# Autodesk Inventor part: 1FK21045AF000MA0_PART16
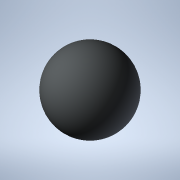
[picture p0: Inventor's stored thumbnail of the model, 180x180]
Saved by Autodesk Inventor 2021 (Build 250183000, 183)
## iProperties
Created: 2025-04
Part Number: 1FK21045AF000MA0_PART16
Material: Generic
Catalog Web Link: www.3dfindit.com
Description: -Servo synchronous motor
Document SubType Name: Modeling
Designer: psAdmin
Mass: 0.137258 g
Surface Area: 1.2868 cm^2
Volume: 0.137258 cm^3
Density: 1 g/cm^3
Appearance: PSOLRGB-212-217-219
Category: PARTsolutions
Title: 1FK21045AF000MA0_PART16
Author: Cadenas PARTsolutions
Comments: Servo synchronous motor
Sending System: PARTsolutions
Preprocessor: ST-DEVELOPER v19.3
PSOL_IDENT_0: {$CADENAS_DATA/23d-libs/siemens_ag/_cat_/8b/0a/1fk21045af000ma0.prj},216 {VTYP=3D},{NB=1FK21045AF000
PSOL_IDENT_1: MA0_PART16},{LINA=1FK21045AF000MA0_PART16},{NN=1FK21045AF000MA0_PART16},{NOPRJ=TRUE},{DATE=19.08.202
PSOL_IDENT_2: 5 14:00:48},{GEOMDATE=30.07.2025 02:00:28},{VERSION=},{LINEID=10},{WBVAR=},{WBNUMERIC=}  {NB=1FK2104
PSOL_IDENT_3: 5AF000MA0_PART16},{LINA=1FK21045AF000MA0_PART16},{KT=DUMMY},{PREVIEW=../../../_pool_/a9/69/p_d211_xx
PSOL_IDENT_4: _00818j.png},{DESCSHORT=SIMOTICS S-1FK2 HD, SINAMICS S210 3AC 400V-480V, 2.4 Nm, 3000 rpm},{DESCLONG=
PSOL_IDENT_5: SIMOTICS S-1FK2 HD servo motor M0=2.4 Nm; PN = 0.75 kW at nN=3000 rpm (380-480 V); PN = 0.375 kW at
PSOL_IDENT_6: nN=1500 rpm (200-240 V); degree of protection IP64; cylindrical shaft D19x40mm; absolute encoder 22-
PSOL_IDENT_7: bit + 12-bit multiturn (encoder AM22DQC); with OCC interface; plug size M17, rotatable; SIMOTICS S-1
PSOL_IDENT_8: FK2 servomotorfor a wide range of uses in industrial environments. SIMOTICS S‑1FK2 servomotors are c
PSOL_IDENT_9: ompact synchronous motors with a high dynamic performance that set themselves apart as a result of t
PSOL_IDENT_10: heir high power density, degree of protection and overload capability. The motors are available in t
PSOL_IDENT_11: wo variants: as High Dynamic variant (highest dynamic performance as a result of the low intrinsic m
PSOL_IDENT_12: oment of inertia for applications demanding a high dynamic performance with low moved masses) - and
PSOL_IDENT_13: as Compact variant (precise and stable closed-loop control for medium up to large moved masses as a
PSOL_IDENT_14: result of a medium intrinsic moment of inertia). SIMOTICSS‑1FK2 servomotors fully exploit their stre
PSOL_IDENT_15: ngths in a system with the SINAMICSS210 frequency converter and simple connection using the one cabl
PSOL_IDENT_16: e connection (OCC). Advantages include the short control and positioning times, fast and precise cor
PSOL_IDENT_17: rection of disturbing quantities as well as stable control with a high dynamic performance. The serv
PSOL_IDENT_18: o motors can be configured to address a wide range of requirements. For example with and without hol
PSOL_IDENT_19: ding brake, IP64 or IP65 degree of protection, singleturn or multiturn absolute encoders - to name j
PSOL_IDENT_20: ust a few. Further, the servomotors are available in different shaft heights extending from 20 to 10
PSOL_IDENT_21: 0. A shaft sealing ring is available to achieve an IP65 degree of protection and for subsequent moun
PSOL_IDENT_22: ting at the motor or as spare part. SIMOTICS - the optimum motor for each and every motion control a
PSOL_IDENT_23: pplication.},{INTNO=195125050112},{SUPPLIERALTNO=1FK2104-5AF00-0MA0},{MANUID=1FK21045AF000MA0},{MANU
PSOL_IDENT_24: NAME=Siemens},{MANUTYPEDESC=Synchronous motor 1FK2-HD 2.4 NM},{AAU732=SIMOTICS},{AAO057=S-1FK2},{AAU
PSOL_IDENT_25: 734=SIMOTICS S-1FK2 HD servo motor M0=2.4 Nm; PN = 0.75 kW at nN=3000 rpm (380-480 V); PN = 0.375 kW
PSOL_IDENT_26: at nN=1500 rpm (200-240 V); degree of protection IP64; cylindrical shaft D19x40mm; absolute encoder
PSOL_IDENT_27: 22-bit + 12-bit multiturn (encoder AM22DQC); with OCC interface; plug size M17, rotatable;},{AAW338=
PSOL_IDENT_28: Synchronous motor 1FK2-HD 2.4 NM},{AAO742=SIMOTICS},{AAO663=4042948692912},{NOCUPEROU=1},{PRICEQUANT
PSOL_IDENT_29: ITY=1},{QUANTITYMIN=1},{QUANTITYINT=1},{CTN=85015100},{COO=DE},{AAO676=1FK2104-5AF00-0MA0},{AAO677=S
PSOL_IDENT_30: iemens AG},{ORDERUNIT=C62},{CONTENTUNIT=C62}
NB: 1FK21045AF000MA0_PART16
NT: Servo synchronous motor
NBSYN: $MANUID._PART16
LINA: 1FK21045AF000MA0_PART16
CATALOG: SIEMENS
PREVIEW: ../../../_pool_/a9/69/p_d211_xx_00818j.png
DESCSHORT: SIMOTICS S-1FK2 HD, SINAMICS S210 3AC 400V-480V, 2.4 Nm, 3000 rpm
DESCLONG: SIMOTICS S-1FK2 HD servo motor M0=2.4 Nm; PN = 0.75 kW at nN=3000 rpm (380-480 V); PN = 0.375 kW at nN=1500 rpm (200-240 V); degree of protection IP64; cylindri
INTNO: 195125050112
SUPPLIERALTNO: 1FK2104-5AF00-0MA0
MANUID: 1FK21045AF000MA0
MANUNAME: Siemens
MANUTYPEDESC: Synchronous motor 1FK2-HD 2.4 NM
AAU732: SIMOTICS
AAO057: S-1FK2
AAU734: SIMOTICS S-1FK2 HD servo motor M0=2.4 Nm; PN = 0.75 kW at nN=3000 rpm (380-480 V); PN = 0.375 kW at nN=1500 rpm (200-240 V); degree of protection IP64; cylindri
AAW338: Synchronous motor 1FK2-HD 2.4 NM
AAO742: SIMOTICS
AAO663: 4042948692912.0
NOCUPEROU: 1
PRICEQUANTITY: 1
QUANTITYMIN: 1
QUANTITYINT: 1
CTN: 85015100
COO: DE
ARTICLENO: 1FK21045AF000MA0_PART16
BOMINFO: 1FK21045AF000MA0_PART16
CREATOR: CADENAS GmbH
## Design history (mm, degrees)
feature "2025_04_17_15_40_42_0766"
body "Solid1"
